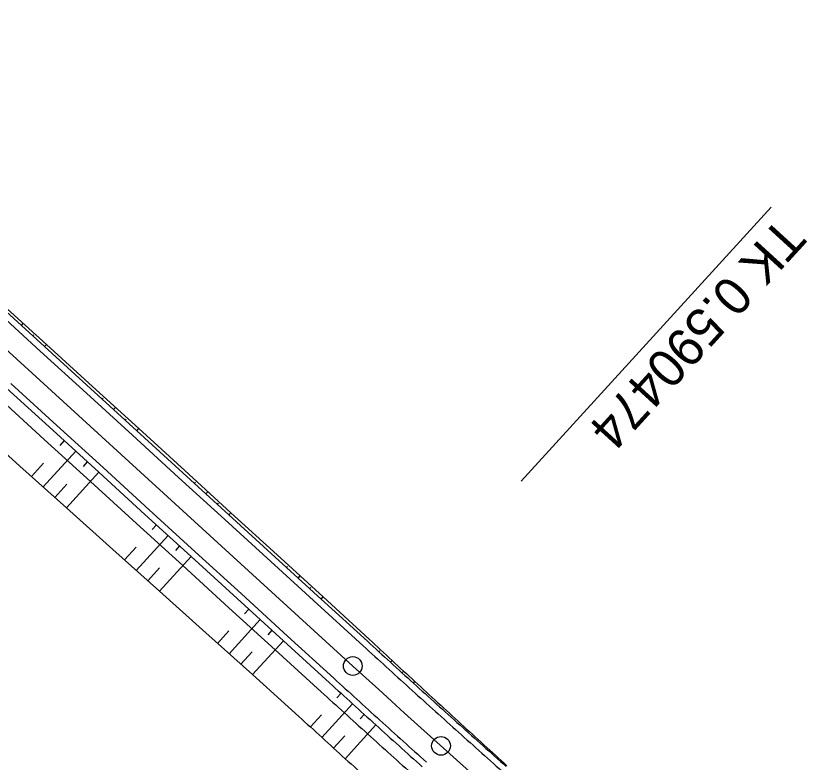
# Model space of a CAD drawing. Extents: x -481656 to -478728, y -1113199 to -1110710.
# Drawn here: x -481324.6 to -481261.3, y -1113006.1 to -1112946.4 of the extents above; entities that cross this region are included whole.
import ezdxf

# ---------------------------------------------------------------- set-up
doc = ezdxf.new("R2010")
doc.units = 0
for name, color, linetype in [('C11_HATCH_SLOPE_L', 7, 'Continuous'), ('C11_HATCH_SLOPE_R', 7, 'Continuous'), ('C11_HECTOMETRY', 7, 'Continuous'), ('C11_HLBODY', 7, 'Continuous'), ('C11_HRANA_TELESO', 7, 'Continuous'), ('C11_KORUNA', 7, 'Continuous'), ('C11_OSA', 7, 'Continuous'), ('C11_PRIKOP', 7, 'Continuous'), ('C11_VOZOVKA', 7, 'Continuous'), ('C11_ZPEVKRAJ', 7, 'Continuous')]:
    doc.layers.add(name, color=color, linetype=linetype)

msp = doc.modelspace()

# ---------------------------------------------------------------- linework, layer by layer
at = {"layer": 'C11_HATCH_SLOPE_L'}
for p, q in [((-481324.186, -1112971.149), (-481324.037, -1112970.985)), ((-481323.263, -1112971.991), (-481323.188, -1112971.908)), ((-481323.112, -1112971.826), (-481323.112, -1112971.826)), ((-481322.339, -1112972.833), (-481322.188, -1112972.668)), ((-481317.721, -1112977.045), (-481317.644, -1112976.96)), ((-481317.567, -1112976.876), (-481317.567, -1112976.876)), ((-481316.798, -1112977.887), (-481316.643, -1112977.717)), ((-481315.874, -1112978.73), (-481315.796, -1112978.644)), ((-481315.718, -1112978.559), (-481315.718, -1112978.559)), ((-481314.95, -1112979.572), (-481314.794, -1112979.401)), ((-481310.333, -1112983.784), (-481310.254, -1112983.697)), ((-481310.174, -1112983.61), (-481310.174, -1112983.61)), ((-481309.409, -1112984.626), (-481309.25, -1112984.451)), ((-481308.486, -1112985.468), (-481308.406, -1112985.38)), ((-481308.325, -1112985.293), (-481308.325, -1112985.293)), ((-481307.562, -1112986.311), (-481307.401, -1112986.135)), ((-481302.944, -1112990.522), (-481302.863, -1112990.434)), ((-481302.782, -1112990.345), (-481302.782, -1112990.345)), ((-481302.021, -1112991.365), (-481301.859, -1112991.188)), ((-481301.097, -1112992.207), (-481301.017, -1112992.119)), ((-481300.936, -1112992.031), (-481300.936, -1112992.031)), ((-481300.174, -1112993.05), (-481300.013, -1112992.874)), ((-481295.557, -1112997.26), (-481295.487, -1112997.184)), ((-481295.418, -1112997.108), (-481295.418, -1112997.108)), ((-481294.634, -1112998.1), (-481294.503, -1112997.956)), ((-481293.71, -1112998.938), (-481293.648, -1112998.87)), ((-481293.586, -1112998.802), (-481293.586, -1112998.802)), ((-481292.786, -1112999.776), (-481292.669, -1112999.648)), ((-481288.15, -1113003.951), (-481288.11, -1113003.906)), ((-481288.07, -1113003.861), (-481288.07, -1113003.861)), ((-481287.22, -1113004.782), (-481287.147, -1113004.701)), ((-481286.289, -1113005.613), (-481286.256, -1113005.576)), ((-481286.224, -1113005.54), (-481286.224, -1113005.54))]:
    msp.add_line(p, q, dxfattribs=at)
at = {"layer": 'C11_HATCH_SLOPE_R'}
for p, q in [((-481320.754, -1112980.37), (-481321.095, -1112980.744)), ((-481319.83, -1112981.212), (-481322.439, -1112984.073)), ((-481322.403, -1112982.178), (-481323.37, -1112983.238)), ((-481318.906, -1112982.055), (-481319.246, -1112982.428)), ((-481317.983, -1112982.897), (-481320.578, -1112985.742)), ((-481320.548, -1112983.854), (-481321.508, -1112984.907)), ((-481313.365, -1112987.109), (-481313.702, -1112987.479)), ((-481312.442, -1112987.951), (-481314.993, -1112990.748)), ((-481314.982, -1112988.882), (-481315.924, -1112989.914)), ((-481311.518, -1112988.793), (-481311.854, -1112989.162)), ((-481310.594, -1112989.636), (-481313.131, -1112992.417)), ((-481313.126, -1112990.557), (-481314.062, -1112991.583)), ((-481305.977, -1112993.847), (-481306.311, -1112994.213)), ((-481305.053, -1112994.69), (-481307.547, -1112997.424)), ((-481304.129, -1112995.532), (-481304.462, -1112995.896)), ((-481307.561, -1112995.584), (-481308.478, -1112996.59)), ((-481303.206, -1112996.374), (-481305.685, -1112999.092)), ((-481305.706, -1112997.26), (-481306.616, -1112998.258)), ((-481298.587, -1113000.587), (-481298.917, -1113000.948)), ((-481297.661, -1113001.43), (-481300.114, -1113004.129)), ((-481300.143, -1113002.295), (-481301.04, -1113003.28)), ((-481296.733, -1113002.272), (-481297.061, -1113002.633)), ((-481295.805, -1113003.112), (-481298.259, -1113005.823)), ((-481298.288, -1113003.985), (-481299.187, -1113004.976))]:
    msp.add_line(p, q, dxfattribs=at)
at = {"layer": 'C11_HECTOMETRY'}
msp.add_circle((-481290.582, -1113004.792), 0.75, dxfattribs=at)
at = {"layer": 'C11_HLBODY'}
msp.add_line((-481264.154, -1112961.68), (-481284.168, -1112983.624), dxfattribs=at)
msp.add_circle((-481297.645, -1112998.401), 0.75, dxfattribs=at)
at = {"layer": 'C11_HRANA_TELESO'}
for p, q in [((-481325.886, -1112969.303), (-481322.188, -1112972.668)), ((-481322.188, -1112972.668), (-481318.491, -1112976.034)), ((-481318.491, -1112976.034), (-481314.794, -1112979.401)), ((-481328.022, -1112979.065), (-481324.301, -1112982.404)), ((-481314.794, -1112979.401), (-481311.098, -1112982.768)), ((-481324.301, -1112982.404), (-481320.578, -1112985.742)), ((-481311.098, -1112982.768), (-481307.401, -1112986.135)), ((-481320.578, -1112985.742), (-481316.854, -1112989.08)), ((-481307.401, -1112986.135), (-481303.705, -1112989.502)), ((-481316.854, -1112989.08), (-481313.131, -1112992.417)), ((-481303.705, -1112989.502), (-481300.013, -1112992.874)), ((-481313.131, -1112992.417), (-481309.409, -1112995.756)), ((-481300.013, -1112992.874), (-481296.334, -1112996.259)), ((-481309.409, -1112995.756), (-481305.685, -1112999.092)), ((-481305.685, -1112999.092), (-481301.964, -1113002.433))]:
    msp.add_line(p, q, dxfattribs=at)
for centre, radius, start, end in [((-478855.272, -1110360.177), 3592.73, 227.199736, 227.279331), ((-480481.437, -1112118.658), 1197.598, 227.360553, 227.599294), ((-478858.068, -1110334.99), 3617.717, 227.504256, 227.583797), ((-480481.223, -1112118.795), 1197.641, 227.587328, 227.826069), ((-480504.17, -1112098.337), 1205.863, 228.812678, 229.051444)]:
    msp.add_arc(centre, radius, start, end, dxfattribs=at)
at = {"layer": 'C11_KORUNA'}
for p, q in [((-481326.033, -1112969.464), (-481322.339, -1112972.833)), ((-481322.339, -1112972.833), (-481318.645, -1112976.203)), ((-481325.371, -1112976.158), (-481321.677, -1112979.528)), ((-481318.645, -1112976.203), (-481314.95, -1112979.572)), ((-481321.677, -1112979.528), (-481317.983, -1112982.897)), ((-481314.95, -1112979.572), (-481311.256, -1112982.941)), ((-481317.983, -1112982.897), (-481314.289, -1112986.266)), ((-481311.256, -1112982.941), (-481307.562, -1112986.311)), ((-481314.289, -1112986.266), (-481310.594, -1112989.636)), ((-481307.562, -1112986.311), (-481303.868, -1112989.68)), ((-481310.594, -1112989.636), (-481306.9, -1112993.005)), ((-481303.868, -1112989.68), (-481300.174, -1112993.05)), ((-481306.9, -1112993.005), (-481303.206, -1112996.374)), ((-481300.174, -1112993.05), (-481296.479, -1112996.419)), ((-481303.206, -1112996.374), (-481299.512, -1112999.744))]:
    msp.add_line(p, q, dxfattribs=at)
for centre, radius, start, end in [((-478877.782, -1110339.099), 3593.25, 227.691481, 227.771072), ((-478871.729, -1110332.438), 3606.75, 227.691528, 227.771092), ((-480489, -1112111.782), 1197.75, 227.849589, 228.088322), ((-480489, -1112111.782), 1202.25, 227.849589, 228.088322), ((-480489, -1112111.782), 1197.75, 228.088322, 228.327056)]:
    msp.add_arc(centre, radius, start, end, dxfattribs=at)
at = {"layer": 'C11_OSA'}
msp.add_line((-481354.685, -1112946.378), (-481297.645, -1112998.401), dxfattribs=at)
msp.add_arc((-480489, -1112111.782), 1200, 227.633469, 229.772919, dxfattribs=at)
at = {"layer": 'C11_PRIKOP'}
for p, q in [((-481326.059, -1112976.912), (-481322.361, -1112980.277)), ((-481322.361, -1112980.277), (-481318.663, -1112983.642)), ((-481318.663, -1112983.642), (-481314.964, -1112987.007)), ((-481314.964, -1112987.007), (-481311.266, -1112990.372)), ((-481311.266, -1112990.372), (-481307.568, -1112993.737)), ((-481307.568, -1112993.737), (-481303.87, -1112997.102)), ((-481303.87, -1112997.102), (-481300.172, -1113000.467))]:
    msp.add_line(p, q, dxfattribs=at)
for centre, radius, start, end in [((-478873.53, -1110328.177), 3609.671, 227.758172, 227.837731), ((-480490.048, -1112110.838), 1203.221, 227.916725, 228.155458)]:
    msp.add_arc(centre, radius, start, end, dxfattribs=at)
at = {"layer": 'C11_VOZOVKA'}
for p, q in [((-481326.37, -1112969.833), (-481322.676, -1112973.203)), ((-481322.676, -1112973.203), (-481318.982, -1112976.572)), ((-481325.034, -1112975.789), (-481321.34, -1112979.158)), ((-481318.982, -1112976.572), (-481315.287, -1112979.942)), ((-481321.34, -1112979.158), (-481317.646, -1112982.528)), ((-481315.287, -1112979.942), (-481311.593, -1112983.311)), ((-481317.646, -1112982.528), (-481313.952, -1112985.897)), ((-481311.593, -1112983.311), (-481307.899, -1112986.68)), ((-481313.952, -1112985.897), (-481310.257, -1112989.266)), ((-481307.899, -1112986.68), (-481304.205, -1112990.05)), ((-481310.257, -1112989.266), (-481306.563, -1112992.636)), ((-481304.205, -1112990.05), (-481300.51, -1112993.419)), ((-481306.563, -1112992.636), (-481302.869, -1112996.005)), ((-481300.51, -1112993.419), (-481296.816, -1112996.788)), ((-481302.869, -1112996.005), (-481299.175, -1112999.374))]:
    msp.add_line(p, q, dxfattribs=at)
for centre, radius, start, end in [((-478877.109, -1110338.359), 3594.75, 227.691486, 227.771075), ((-478872.402, -1110333.178), 3605.25, 227.691525, 227.771092), ((-480489, -1112111.782), 1198.25, 227.849589, 228.088322), ((-480489, -1112111.782), 1201.75, 227.849589, 228.088322), ((-480489, -1112111.782), 1198.25, 228.088322, 228.327056)]:
    msp.add_arc(centre, radius, start, end, dxfattribs=at)
at = {"layer": 'C11_ZPEVKRAJ'}
for p, q in [((-481326.37, -1112969.833), (-481322.676, -1112973.203)), ((-481322.676, -1112973.203), (-481318.982, -1112976.572)), ((-481325.034, -1112975.789), (-481321.34, -1112979.158)), ((-481318.982, -1112976.572), (-481315.287, -1112979.942)), ((-481321.34, -1112979.158), (-481317.646, -1112982.528)), ((-481315.287, -1112979.942), (-481311.593, -1112983.311)), ((-481317.646, -1112982.528), (-481313.952, -1112985.897)), ((-481311.593, -1112983.311), (-481307.899, -1112986.68)), ((-481313.952, -1112985.897), (-481310.257, -1112989.266)), ((-481307.899, -1112986.68), (-481304.205, -1112990.05)), ((-481310.257, -1112989.266), (-481306.563, -1112992.636)), ((-481304.205, -1112990.05), (-481300.51, -1112993.419)), ((-481306.563, -1112992.636), (-481302.869, -1112996.005)), ((-481300.51, -1112993.419), (-481296.816, -1112996.788)), ((-481302.869, -1112996.005), (-481299.175, -1112999.374))]:
    msp.add_line(p, q, dxfattribs=at)
for centre, radius, start, end in [((-478877.109, -1110338.359), 3594.75, 227.691486, 227.771075), ((-478872.402, -1110333.178), 3605.25, 227.691525, 227.771092), ((-480489, -1112111.782), 1198.25, 227.849589, 228.088322), ((-480489, -1112111.782), 1201.75, 227.849589, 228.088322), ((-480489, -1112111.782), 1198.25, 228.088322, 228.327056)]:
    msp.add_arc(centre, radius, start, end, dxfattribs=at)

# ---------------------------------------------------------------- texts
at = {"layer": 'C11_HLBODY'}
msp.add_text('TK 0.590474', height=2.999, rotation=227.63348, dxfattribs=at).set_placement((-481263.415, -1112962.353))

doc.saveas('drawing.dxf')
